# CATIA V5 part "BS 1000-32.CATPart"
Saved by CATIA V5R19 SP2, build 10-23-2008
Part number: BS 1000-32
Bounding box of the stored display mesh (mm): x -24.865 to 24.865, y -24.997 to 24.997, z 0 to 102
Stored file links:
  C:\Users\Bora\Desktop\3D Katı model\BS serisi\BS 1000\BS 1000-32.CATPart
  C:\Program Files\Dassault Systemes\B19\intel_a\reffiles\standard\MetricThickPitch.txt
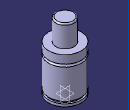
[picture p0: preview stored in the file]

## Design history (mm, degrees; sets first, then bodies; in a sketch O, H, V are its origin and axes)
Body1 (main body)
  Sketch1 on yz-plane, origin (0, 0, 0), H (0, 1, 0), V (0, 0, 1)
    point P1 (14, 100)
    point P4 (25, 56.5)
    point P5 (25, 52.5)
    point P9 (25, 56.5)
    point P10 (25, 52.5)
    point P11 (14, 100)
    point P13 (22.5, 4)
    point P15 (22.5, 4)
    line L1 (14, 100) -> (14, 69)
    line L2 (25, 69) -> (25, 56.5)
    line L3 (25, 52.5) -> (25, 7.5)
    line L4 (25, 4) -> (25, 0)
    arc A1 centre (25, 54.5) radius 2 from (25, 56.5) to (25, 52.5) ccw
    arc A2 centre (12, 100) radius 2 from (14, 100) to (12, 102) ccw
    line L5 (22.5, 7.5) -> (22.5, 4)
    line L6 (12, 102) -> (0, 102)
    point P16 (0, 102)
    line L7 (14, 69) -> (25, 69)
    line L8 (22.5, 7.5) -> (25, 7.5)
    line L9 (22.5, 4) -> (25, 4)
    line L10 (0, 0) -> (25, 0)
    coincidence: P16 V, P1 P11, P4 P9, P5 P10, P13 P15
    tangency: L6 A2
    horizontal: L7 H, L8 H, L9 H, L10 H
  Shaft1: profile Sketch1, axis Sketch1.V, angle 360
  Sketch2 on face of Shaft1 from Sketch1.L10, origin (0, 0, 0), H (1, 0, 0), V (0, -1, 0)
    point P1 (10, 0)
    distance P1 V = 10
  Hole1: placed by Sketch2, at (10, 0, 0) direction (0, 0, 1), diameter 6.647, depth 6, threaded "M8", thread diameter 8, thread depth 6, pitch 1.25
  CircPattern1: of Hole1, instances 2, angular step 180, axis from xy-plane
